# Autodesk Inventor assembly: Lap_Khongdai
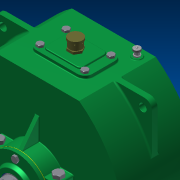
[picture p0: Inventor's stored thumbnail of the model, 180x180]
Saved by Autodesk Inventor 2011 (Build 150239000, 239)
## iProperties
Created: 2011-05
Part Number: Lap_Khongdai
Document SubType Name: Assembly
Designer: 904Chiaki
Author: 904Chiaki
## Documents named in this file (39)
- E:\2.FINISH\DOAN_CTM_final\Lap_Khongdai.iam
- E:\2.FINISH\DOAN_CTM_final\Thanhop.ipt
- E:\2.FINISH\DOAN_CTM_final\Bearing2_1.ipt
- E:\2.FINISH\DOAN_CTM_final\Bearing2_2.ipt
- E:\2.FINISH\DOAN_CTM_final\Bearing3.ipt
- E:\2.FINISH\DOAN_CTM_final\Naphop.ipt
- E:\2.FINISH\DOAN_CTM_final\Napquansat.ipt
- E:\2.FINISH\DOAN_CTM_final\Nutthonghoi.iam
- E:\2.FINISH\DOAN_CTM_final\Chotdinhvi.ipt
- E:\2.FINISH\DOAN_CTM_final\Bulongbich.ipt
- E:\2.FINISH\DOAN_CTM_final\Daiocbich.ipt
- E:\2.FINISH\DOAN_CTM_final\Vongdembich.ipt
- E:\2.FINISH\DOAN_CTM_final\BulongCanhO.ipt
- E:\2.FINISH\DOAN_CTM_final\Daioccanho.ipt
- E:\2.FINISH\DOAN_CTM_final\VongdemcanhO.ipt
- E:\2.FINISH\DOAN_CTM_final\Vitghepnapcuatham.ipt
- E:\2.FINISH\DOAN_CTM_final\VongChandau2.ipt
- E:\2.FINISH\DOAN_CTM_final\Shaft3.ipt
- E:\2.FINISH\DOAN_CTM_final\Onglot.ipt
- E:\2.FINISH\DOAN_CTM_final\VongChandau1.ipt
- E:\2.FINISH\DOAN_CTM_final\Lap1_codai\Design Accelerator\Key Connection2.iam
- E:\2.FINISH\DOAN_CTM_final\Lap1_codai\Design Accelerator\Key Connection3.iam
- E:\2.FINISH\DOAN_CTM_final\Trucvit.iam
- E:\2.FINISH\DOAN_CTM_final\Coclot1.ipt
- E:\2.FINISH\DOAN_CTM_final\Coclot2.ipt
- E:\2.FINISH\DOAN_CTM_final\NapO2.ipt
- E:\2.FINISH\DOAN_CTM_final\NapO2_2.ipt
- E:\2.FINISH\DOAN_CTM_final\Vongphot2.ipt
- E:\2.FINISH\DOAN_CTM_final\VongdemnapO2.ipt
- E:\2.FINISH\DOAN_CTM_final\NapO1.ipt
- E:\2.FINISH\DOAN_CTM_final\NapO1_2.ipt
- E:\2.FINISH\DOAN_CTM_final\VongdemNapO1.ipt
- E:\2.FINISH\DOAN_CTM_final\Vongphot1.ipt
- C:\Users\HTYCOON\Documents\Inventor\Content Center Files\R2011\en-US\DIN 910(1)\DIN 910 - M16 x 1.5.ipt
- E:\2.FINISH\DOAN_CTM_final\VitghepnapO.ipt
- E:\2.FINISH\DOAN_CTM_final\Quethamdau.ipt
- C:\Users\HTYCOON\Documents\Inventor\Content Center Files\R2011\en-US\ISO 4035(2)\ISO 4035 - M39ISO.ipt
- E:\2.FINISH\DOAN_CTM_final\Washer 18 GOST 11872-89.ipt
- E:\2.FINISH\DOAN_CTM_final\Banhvit.iam
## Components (95 placed, 37 different names)
1. Thanhop:1 — Mate:42, Flush:7, Mate:65, Mate:69, Mate:75, Mate:79, Mate:83, Mate:87, Mate:105, Mate:107, Mate:109, Mate:111, Mate:124, Angle:6, Mate:154, Mate:155, Angle:13, Angle:19, Angle:21, Angle:22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
2. DIN 628 - T1 7208B - 40 x 80 x 18:1 — Mate:179, Mate:180, Mate:182
3. ISO 355 3DB - 40 x 80 x 19.75:1 — Mate:250, Mate:251, Mate:254
4. ISO 355 3DB - 40 x 80 x 19.75:2 — Mate:248, Mate:249, Mate:251, Mate:252
5. ISO 355 2CE - 70 x 110 x 31:1 — Mate:126, Flush:12
6. ISO 355 2CE - 70 x 110 x 31:2 — Mate:123, Flush:13, Mate:128, Mate:130, Mate:260
7. Naphop:1 — Mate:42, Flush:7, Mate:45, Flush:8, Flush:9, Mate:50, Flush:10, Mate:51, Flush:11, Mate:52, Mate:53, Mate:54, Mate:55, Mate:56, Mate:57, Mate:58, Mate:59, Mate:60, Mate:61, Mate:62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
8. Napquansat:1 — Mate:43, Mate:44, Mate:45, Flush:8, Flush:9, Mate:112, Mate:113, Mate:114, Mate:115, Mate:116, Mate:117, Mate:118, Mate:119
9. Nutthonghoi:2 [sub-assembly] — Mate:43, Mate:44, Angle:32
10. ISO 2338 4 h8 x 55 - B:1 — Mate:51, Flush:11
11. ISO 2338 4 h8 x 55 - B:2 — Mate:50, Flush:10
12. ISO 4014 M14 x 70:1 — Mate:62, Mate:63, Mate:86
13. ISO 7417 M14:1 — Mate:66, Mate:67
14. ISO 7092 ST 14 - 140 HV:1 — Mate:64, Mate:65, Mate:67
15. ISO 4014 M14 x 70:2 — Mate:60, Mate:61, Mate:78
16. ISO 7417 M14:2 — Mate:70, Mate:71
17. ISO 7092 ST 14 - 140 HV:2 — Mate:68, Mate:69, Mate:71
18. ISO 4014 M14 x 70:3 — Mate:58, Mate:59, Mate:74
19. ISO 7417 M14:3 — Mate:72, Mate:73, Mate:74
20. ISO 7092 ST 14 - 140 HV:3 — Mate:72, Mate:73, Mate:75
21. ISO 4014 M14 x 70:4 — Mate:56, Mate:57, Mate:64, Mate:66
22. ISO 7417 M14:4 — Mate:76, Mate:77, Mate:78
23. ISO 7092 ST 14 - 140 HV:4 — Mate:76, Mate:77, Mate:79
24. ISO 4014 M14 x 70:5 — Mate:54, Mate:55, Mate:82
25. ISO 7417 M14:5 — Mate:80, Mate:81, Mate:82
26. ISO 7092 ST 14 - 140 HV:5 — Mate:80, Mate:81, Mate:83
27. ISO 4014 M14 x 70:6 — Mate:52, Mate:53, Mate:68, Mate:70
28. ISO 7417 M14:6 — Mate:84, Mate:85, Mate:86
29. ISO 7092 ST 14 - 140 HV:6 — Mate:84, Mate:85, Mate:87
30. ISO 4014 M16 x 120:1 — Mate:93, Mate:94, Mate:106
31. ISO 7414 M16:1 — Mate:96, Mate:97, Mate:104
32. ISO 7092 ST 16 - 140 HV:1 — Mate:96, Mate:97, Mate:105
33. ISO 4014 M16 x 120:2 — Mate:92, Mate:95, Mate:104
34. ISO 7414 M16:2 — Mate:98, Mate:99, Mate:106
35. ISO 7092 ST 16 - 140 HV:2 — Mate:98, Mate:99, Mate:107
36. ISO 4014 M16 x 120:3 — Mate:90, Mate:91, Mate:110
37. ISO 7414 M16:3 — Mate:100, Mate:101, Mate:108
38. ISO 7092 ST 16 - 140 HV:3 — Mate:100, Mate:101, Mate:109
39. ISO 4014 M16 x 120:4 — Mate:88, Mate:89, Mate:108
40. ISO 7414 M16:4 — Mate:102, Mate:103, Mate:110
41. ISO 7092 ST 16 - 140 HV:4 — Mate:102, Mate:103, Mate:111
42. ISO 4017 M10 x 20:1 — Mate:112, Mate:113, Angle:31
43. ISO 4017 M10 x 20:2 — Mate:114, Mate:117, Angle:28
44. ISO 4017 M10 x 20:3 — Mate:115, Mate:118, Angle:29
45. ISO 4017 M10 x 20:4 — Mate:116, Mate:119, Angle:30
46. VongChandau2:1 — Mate:127, Mate:129
47. VongChandau2:2 — Mate:123, Mate:130, Mate:131, Mate:133
48. Shaft:3 — Mate:124, Mate:126, Mate:127, Flush:12, Flush:13, Mate:128, Angle:6, Mate:129, Mate:131, Mate:132, Flush:14, Angle:11, Mate:140, Mate:157, Mate:158, Mate:161, Angle:25, Mate:257, Mate:259
49. Onglot:1 — Mate:132, Mate:133
50. VongChandau1:1 — Mate:181, Mate:182
51. VongChandau1:2 — Mate:183, Mate:252
52. Key Connection:1 [sub-assembly]
53. Key Connection:2 [sub-assembly] — Flush:14, Angle:11, Mate:140, Mate:258
54. Trucvit:1 [sub-assembly] — Mate:177, Mate:179, Mate:180, Mate:181, Mate:183, Mate:184, Mate:187, Mate:188, Angle:25, Mate:248, Mate:249, Mate:250, Mate:253, Angle:26, Mate:255
55. Coclot1:1 — Mate:184, Mate:185, Mate:186, Angle:23, Angle:24
56. Coclot2:1 — Mate:154, Mate:155, Angle:13, Mate:166, Mate:167, Mate:173
57. NapO2:1 — Mate:159, Angle:18, Mate:164, Mate:214, Mate:215, Mate:216, Mate:217, Mate:218, Mate:219, Mate:232, Mate:233, Mate:234, Mate:235, Mate:236, Mate:237
58. NapO2_2:1 — Mate:156, Tangent:1, Angle:15, Mate:165, Mate:202, Mate:203, Mate:204, Mate:205, Mate:206, Mate:207, Mate:244, Mate:245, Mate:260
59. Vongphot2:1 — Mate:156, Tangent:1, Mate:157
60. VongdemnapO2:1 — Mate:160, Mate:161, Angle:16, Mate:165
61. VongdemnapO2:2 — Mate:162, Mate:163, Angle:17, Mate:164
62. NapO1:1 — Mate:170, Tangent:2, Angle:21, Mate:188, Mate:189, Mate:208, Mate:209, Mate:210, Mate:211, Mate:212, Mate:213, Mate:238, Mate:239, Mate:240, Mate:241, Mate:242, Mate:243
63. NapO1_2:1 — Mate:173, Mate:174, Angle:22, Mate:220, Mate:221, Mate:222, Mate:223, Mate:224, Mate:225, Mate:226, Mate:227, Mate:228, Mate:229, Mate:230, Mate:231
64. VongdemNapO1:1 — Mate:186, Mate:187, Angle:24, Mate:189
65. Vongphot1:1 — Mate:170, Tangent:2
66. VongdemNapO1:2 — Mate:166, Mate:167, Angle:19, Mate:174
67. DIN 910 (Fine Thread) M16 x 1.5:1 — Mate:198, Mate:199
68. ISO 4017 M10 x 25:1 — Mate:220, Mate:230
69. ISO 4017 M10 x 25:2 — Mate:225, Mate:228
70. ISO 4017 M10 x 25:3 — Mate:224, Mate:227
71. ISO 4017 M10 x 25:4 — Mate:223, Mate:226
72. ISO 4017 M10 x 25:5 — Mate:222, Mate:229
73. ISO 4017 M10 x 25:6 — Mate:221, Mate:231
74. ISO 4017 M10 x 25:7 — Mate:214, Mate:236
75. ISO 4017 M10 x 25:8 — Mate:215, Mate:235
76. ISO 4017 M10 x 25:9 — Mate:216, Mate:234
77. ISO 4017 M10 x 25:10 — Mate:217, Mate:232
78. ISO 4017 M10 x 25:11 — Mate:218, Mate:233
79. ISO 4017 M10 x 25:12 — Mate:219, Mate:237
80. ISO 4017 M10 x 25:13 — Mate:208, Mate:242
81. ISO 4017 M10 x 25:14 — Mate:209, Mate:243
82. ISO 4017 M10 x 25:15 — Mate:210, Mate:238
83. ISO 4017 M10 x 25:16 — Mate:211, Mate:241
84. ISO 4017 M10 x 25:17 — Mate:212, Mate:240
85. ISO 4017 M10 x 25:18 — Mate:213, Mate:239
86. ISO 4017 M10 x 25:19 — Mate:202, Flush:19, Mate:245
87. ISO 4017 M10 x 25:20 — Mate:207, Flush:16, Flush:18
88. ISO 4017 M10 x 25:21 — Mate:206, Flush:16, Flush:17
89. ISO 4017 M10 x 25:22 — Mate:205, Flush:17
90. ISO 4017 M10 x 25:23 — Mate:204, Mate:244
91. ISO 4017 M10 x 25:24 — Mate:203, Flush:18, Flush:19
92. Quethamdau:1 — Mate:246, Mate:247, Angle:27
93. ISO 4035 M39:1 — Mate:255, Mate:256
94. Washer GOST 11872-89 18:1 — Mate:253, Mate:254, Angle:26, Mate:256
95. Banhvit:1 [sub-assembly] — Mate:257, Mate:258, Mate:259
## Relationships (209: Mate 175, Angle 20, Flush 12, Tangent 2)
- Mate:42: Thanhop:1 ↔ Naphop:1
- Flush:7: Thanhop:1 ↔ Naphop:1
- Mate:43: Napquansat:1 ↔ Nutthonghoi:2
- Mate:44: Napquansat:1 ↔ Nutthonghoi:2
- Mate:45: Naphop:1 ↔ Napquansat:1
- Flush:8: Naphop:1 ↔ Napquansat:1
- Flush:9: Naphop:1 ↔ Napquansat:1
- Mate:50: Naphop:1 ↔ ISO 2338 4 h8 x 55 - B:2
- Flush:10: Naphop:1 ↔ ISO 2338 4 h8 x 55 - B:2
- Mate:51: Naphop:1 ↔ ISO 2338 4 h8 x 55 - B:1
- Flush:11: Naphop:1 ↔ ISO 2338 4 h8 x 55 - B:1
- Mate:52: Naphop:1 ↔ ISO 4014 M14 x 70:6
- Mate:53: Naphop:1 ↔ ISO 4014 M14 x 70:6
- Mate:54: Naphop:1 ↔ ISO 4014 M14 x 70:5
- Mate:55: Naphop:1 ↔ ISO 4014 M14 x 70:5
- Mate:56: Naphop:1 ↔ ISO 4014 M14 x 70:4
- Mate:57: Naphop:1 ↔ ISO 4014 M14 x 70:4
- Mate:58: Naphop:1 ↔ ISO 4014 M14 x 70:3
- Mate:59: Naphop:1 ↔ ISO 4014 M14 x 70:3
- Mate:60: Naphop:1 ↔ ISO 4014 M14 x 70:2
- Mate:61: Naphop:1 ↔ ISO 4014 M14 x 70:2
- Mate:62: Naphop:1 ↔ ISO 4014 M14 x 70:1
- Mate:63: Naphop:1 ↔ ISO 4014 M14 x 70:1
- Mate:64: ISO 7092 ST 14 - 140 HV:1 ↔ ISO 4014 M14 x 70:4
- Mate:65: Thanhop:1 ↔ ISO 7092 ST 14 - 140 HV:1
- Mate:66: ISO 7417 M14:1 ↔ ISO 4014 M14 x 70:4
- Mate:67: ISO 7417 M14:1 ↔ ISO 7092 ST 14 - 140 HV:1
- Mate:68: ISO 7092 ST 14 - 140 HV:2 ↔ ISO 4014 M14 x 70:6
- Mate:69: Thanhop:1 ↔ ISO 7092 ST 14 - 140 HV:2
- Mate:70: ISO 7417 M14:2 ↔ ISO 4014 M14 x 70:6
- Mate:71: ISO 7417 M14:2 ↔ ISO 7092 ST 14 - 140 HV:2
- Mate:72: ISO 7417 M14:3 ↔ ISO 7092 ST 14 - 140 HV:3
- Mate:73: ISO 7417 M14:3 ↔ ISO 7092 ST 14 - 140 HV:3
- Mate:74: ISO 4014 M14 x 70:3 ↔ ISO 7417 M14:3
- Mate:75: Thanhop:1 ↔ ISO 7092 ST 14 - 140 HV:3
- Mate:76: ISO 7417 M14:4 ↔ ISO 7092 ST 14 - 140 HV:4
- Mate:77: ISO 7417 M14:4 ↔ ISO 7092 ST 14 - 140 HV:4
- Mate:78: ISO 4014 M14 x 70:2 ↔ ISO 7417 M14:4
- Mate:79: Thanhop:1 ↔ ISO 7092 ST 14 - 140 HV:4
- Mate:80: ISO 7417 M14:5 ↔ ISO 7092 ST 14 - 140 HV:5
- Mate:81: ISO 7417 M14:5 ↔ ISO 7092 ST 14 - 140 HV:5
- Mate:82: ISO 4014 M14 x 70:5 ↔ ISO 7417 M14:5
- Mate:83: Thanhop:1 ↔ ISO 7092 ST 14 - 140 HV:5
- Mate:84: ISO 7417 M14:6 ↔ ISO 7092 ST 14 - 140 HV:6
- Mate:85: ISO 7417 M14:6 ↔ ISO 7092 ST 14 - 140 HV:6
- Mate:86: ISO 4014 M14 x 70:1 ↔ ISO 7417 M14:6
- Mate:87: Thanhop:1 ↔ ISO 7092 ST 14 - 140 HV:6
- Mate:88: Naphop:1 ↔ ISO 4014 M16 x 120:4
- Mate:89: Naphop:1 ↔ ISO 4014 M16 x 120:4
- Mate:90: Naphop:1 ↔ ISO 4014 M16 x 120:3
- Mate:91: Naphop:1 ↔ ISO 4014 M16 x 120:3
- Mate:92: Naphop:1 ↔ ISO 4014 M16 x 120:2
- Mate:93: Naphop:1 ↔ ISO 4014 M16 x 120:1
- Mate:94: Naphop:1 ↔ ISO 4014 M16 x 120:1
- Mate:95: Naphop:1 ↔ ISO 4014 M16 x 120:2
- Mate:96: ISO 7414 M16:1 ↔ ISO 7092 ST 16 - 140 HV:1
- Mate:97: ISO 7414 M16:1 ↔ ISO 7092 ST 16 - 140 HV:1
- Mate:98: ISO 7414 M16:2 ↔ ISO 7092 ST 16 - 140 HV:2
- Mate:99: ISO 7414 M16:2 ↔ ISO 7092 ST 16 - 140 HV:2
- Mate:100: ISO 7414 M16:3 ↔ ISO 7092 ST 16 - 140 HV:3
- Mate:101: ISO 7414 M16:3 ↔ ISO 7092 ST 16 - 140 HV:3
- Mate:102: ISO 7414 M16:4 ↔ ISO 7092 ST 16 - 140 HV:4
- Mate:103: ISO 7414 M16:4 ↔ ISO 7092 ST 16 - 140 HV:4
- Mate:104: ISO 7414 M16:1 ↔ ISO 4014 M16 x 120:2
- Mate:105: Thanhop:1 ↔ ISO 7092 ST 16 - 140 HV:1
- Mate:106: ISO 4014 M16 x 120:1 ↔ ISO 7414 M16:2
- Mate:107: Thanhop:1 ↔ ISO 7092 ST 16 - 140 HV:2
- Mate:108: ISO 7414 M16:3 ↔ ISO 4014 M16 x 120:4
- Mate:109: Thanhop:1 ↔ ISO 7092 ST 16 - 140 HV:3
- Mate:110: ISO 4014 M16 x 120:3 ↔ ISO 7414 M16:4
- Mate:111: Thanhop:1 ↔ ISO 7092 ST 16 - 140 HV:4
- Mate:112: Napquansat:1 ↔ ISO 4017 M10 x 20:1
- Mate:113: Napquansat:1 ↔ ISO 4017 M10 x 20:1
- Mate:114: Napquansat:1 ↔ ISO 4017 M10 x 20:2
- Mate:115: Napquansat:1 ↔ ISO 4017 M10 x 20:3
- Mate:116: Napquansat:1 ↔ ISO 4017 M10 x 20:4
- Mate:117: Napquansat:1 ↔ ISO 4017 M10 x 20:2
- Mate:118: Napquansat:1 ↔ ISO 4017 M10 x 20:3
- Mate:119: Napquansat:1 ↔ ISO 4017 M10 x 20:4
- Mate:123: ISO 355 2CE - 70 x 110 x 31:2 ↔ VongChandau2:2
- Mate:124: Thanhop:1 ↔ Shaft:3
- Mate:126: ISO 355 2CE - 70 x 110 x 31:1 ↔ Shaft:3
- Mate:127: VongChandau2:1 ↔ Shaft:3
- Flush:12: ISO 355 2CE - 70 x 110 x 31:1 ↔ Shaft:3
- Flush:13: ISO 355 2CE - 70 x 110 x 31:2 ↔ Shaft:3
- Mate:128: ISO 355 2CE - 70 x 110 x 31:2 ↔ Shaft:3
- Angle:6: Thanhop:1 ↔ Shaft:3
- Mate:129: VongChandau2:1 ↔ Shaft:3
- Mate:130: ISO 355 2CE - 70 x 110 x 31:2 ↔ VongChandau2:2
- Mate:131: VongChandau2:2 ↔ Shaft:3
- Mate:132: Shaft:3 ↔ Onglot:1
- Mate:133: VongChandau2:2 ↔ Onglot:1
- Flush:14: Shaft:3 ↔ Key Connection:2
- Angle:11: Shaft:3 ↔ Key Connection:2
- Mate:140: Shaft:3 ↔ Key Connection:2
- Mate:154: Thanhop:1 ↔ Coclot2:1
- Mate:155: Thanhop:1 ↔ Coclot2:1
- Angle:13: Thanhop:1 ↔ Coclot2:1
- Mate:156: NapO2_2:1 ↔ Vongphot2:1
- Tangent:1: NapO2_2:1 ↔ Vongphot2:1
- Mate:157: Shaft:3 ↔ Vongphot2:1
- Mate:158: Naphop:1 ↔ Shaft:3
- Angle:15: Naphop:1 ↔ NapO2_2:1
- Mate:159: Naphop:1 ↔ NapO2:1
- Mate:160: Naphop:1 ↔ VongdemnapO2:1
- Mate:161: Shaft:3 ↔ VongdemnapO2:1
- Angle:16: Naphop:1 ↔ VongdemnapO2:1
- Mate:162: Naphop:1 ↔ VongdemnapO2:2
- Mate:163: Naphop:1 ↔ VongdemnapO2:2
- Angle:17: Naphop:1 ↔ VongdemnapO2:2
- Angle:18: Naphop:1 ↔ NapO2:1
- Mate:164: NapO2:1 ↔ VongdemnapO2:2
- Mate:165: NapO2_2:1 ↔ VongdemnapO2:1
- Mate:166: Coclot2:1 ↔ VongdemNapO1:2
- Mate:167: Coclot2:1 ↔ VongdemNapO1:2
- Angle:19: Thanhop:1 ↔ VongdemNapO1:2
- Mate:170: NapO1:1 ↔ Vongphot1:1
- Tangent:2: NapO1:1 ↔ Vongphot1:1
- Angle:21: Thanhop:1 ↔ NapO1:1
- Mate:173: Coclot2:1 ↔ NapO1_2:1
- Mate:174: NapO1_2:1 ↔ VongdemNapO1:2
- Angle:22: Thanhop:1 ↔ NapO1_2:1
- Mate:177: Thanhop:1 ↔ Trucvit:1
- Mate:179: DIN 628 - T1 7208B - 40 x 80 x 18:1 ↔ Trucvit:1
- Mate:180: DIN 628 - T1 7208B - 40 x 80 x 18:1 ↔ Trucvit:1
- Mate:181: VongChandau1:1 ↔ Trucvit:1
- Mate:182: DIN 628 - T1 7208B - 40 x 80 x 18:1 ↔ VongChandau1:1
- Mate:183: VongChandau1:2 ↔ Trucvit:1
- Mate:184: Trucvit:1 ↔ Coclot1:1
- Mate:185: Thanhop:1 ↔ Coclot1:1
- Mate:186: Coclot1:1 ↔ VongdemNapO1:1
- Mate:187: Trucvit:1 ↔ VongdemNapO1:1
- Angle:23: Thanhop:1 ↔ Coclot1:1
- Angle:24: Coclot1:1 ↔ VongdemNapO1:1
- Mate:188: Trucvit:1 ↔ NapO1:1
- Mate:189: NapO1:1 ↔ VongdemNapO1:1
- Angle:25: Shaft:3 ↔ Trucvit:1
- Mate:198: Thanhop:1 ↔ DIN 910 (Fine Thread) M16 x 1.5:1
- Mate:199: Thanhop:1 ↔ DIN 910 (Fine Thread) M16 x 1.5:1
- Mate:202: NapO2_2:1 ↔ ISO 4017 M10 x 25:19
- Mate:203: NapO2_2:1 ↔ ISO 4017 M10 x 25:24
- Mate:204: NapO2_2:1 ↔ ISO 4017 M10 x 25:23
- Mate:205: NapO2_2:1 ↔ ISO 4017 M10 x 25:22
- Mate:206: NapO2_2:1 ↔ ISO 4017 M10 x 25:21
- Mate:207: NapO2_2:1 ↔ ISO 4017 M10 x 25:20
- Mate:208: NapO1:1 ↔ ISO 4017 M10 x 25:13
- Mate:209: NapO1:1 ↔ ISO 4017 M10 x 25:14
- Mate:210: NapO1:1 ↔ ISO 4017 M10 x 25:15
- Mate:211: NapO1:1 ↔ ISO 4017 M10 x 25:16
- Mate:212: NapO1:1 ↔ ISO 4017 M10 x 25:17
- Mate:213: NapO1:1 ↔ ISO 4017 M10 x 25:18
- Mate:214: NapO2:1 ↔ ISO 4017 M10 x 25:7
- Mate:215: NapO2:1 ↔ ISO 4017 M10 x 25:8
- Mate:216: NapO2:1 ↔ ISO 4017 M10 x 25:9
- Mate:217: NapO2:1 ↔ ISO 4017 M10 x 25:10
- Mate:218: NapO2:1 ↔ ISO 4017 M10 x 25:11
- Mate:219: NapO2:1 ↔ ISO 4017 M10 x 25:12
- Mate:220: NapO1_2:1 ↔ ISO 4017 M10 x 25:1
- Mate:221: NapO1_2:1 ↔ ISO 4017 M10 x 25:6
- Mate:222: NapO1_2:1 ↔ ISO 4017 M10 x 25:5
- Mate:223: NapO1_2:1 ↔ ISO 4017 M10 x 25:4
- Mate:224: NapO1_2:1 ↔ ISO 4017 M10 x 25:3
- Mate:225: NapO1_2:1 ↔ ISO 4017 M10 x 25:2
- Mate:226: NapO1_2:1 ↔ ISO 4017 M10 x 25:4
- Mate:227: NapO1_2:1 ↔ ISO 4017 M10 x 25:3
- Mate:228: NapO1_2:1 ↔ ISO 4017 M10 x 25:2
- Mate:229: NapO1_2:1 ↔ ISO 4017 M10 x 25:5
- Mate:230: NapO1_2:1 ↔ ISO 4017 M10 x 25:1
- Mate:231: NapO1_2:1 ↔ ISO 4017 M10 x 25:6
- Mate:232: NapO2:1 ↔ ISO 4017 M10 x 25:10
- Mate:233: NapO2:1 ↔ ISO 4017 M10 x 25:11
- Mate:234: NapO2:1 ↔ ISO 4017 M10 x 25:9
- Mate:235: NapO2:1 ↔ ISO 4017 M10 x 25:8
- Mate:236: NapO2:1 ↔ ISO 4017 M10 x 25:7
- Mate:237: NapO2:1 ↔ ISO 4017 M10 x 25:12
- Mate:238: NapO1:1 ↔ ISO 4017 M10 x 25:15
- Mate:239: NapO1:1 ↔ ISO 4017 M10 x 25:18
- Mate:240: NapO1:1 ↔ ISO 4017 M10 x 25:17
- Mate:241: NapO1:1 ↔ ISO 4017 M10 x 25:16
- Mate:242: NapO1:1 ↔ ISO 4017 M10 x 25:13
- Mate:243: NapO1:1 ↔ ISO 4017 M10 x 25:14
- Mate:244: NapO2_2:1 ↔ ISO 4017 M10 x 25:23
- Flush:16: ISO 4017 M10 x 25:20 ↔ ISO 4017 M10 x 25:21
- Flush:17: ISO 4017 M10 x 25:21 ↔ ISO 4017 M10 x 25:22
- Flush:18: ISO 4017 M10 x 25:20 ↔ ISO 4017 M10 x 25:24
- Flush:19: ISO 4017 M10 x 25:19 ↔ ISO 4017 M10 x 25:24
- Mate:245: NapO2_2:1 ↔ ISO 4017 M10 x 25:19
- Mate:246: Naphop:1 ↔ Quethamdau:1
- Mate:247: Naphop:1 ↔ Quethamdau:1
- Mate:248: ISO 355 3DB - 40 x 80 x 19.75:2 ↔ Trucvit:1
- Mate:249: ISO 355 3DB - 40 x 80 x 19.75:2 ↔ Trucvit:1
- Mate:250: ISO 355 3DB - 40 x 80 x 19.75:1 ↔ Trucvit:1
- Mate:251: ISO 355 3DB - 40 x 80 x 19.75:1 ↔ ISO 355 3DB - 40 x 80 x 19.75:2
- Mate:252: ISO 355 3DB - 40 x 80 x 19.75:2 ↔ VongChandau1:2
- Mate:253: Trucvit:1 ↔ Washer GOST 11872-89 18:1
- Mate:254: ISO 355 3DB - 40 x 80 x 19.75:1 ↔ Washer GOST 11872-89 18:1
- Angle:26: Trucvit:1 ↔ Washer GOST 11872-89 18:1
- Mate:255: Trucvit:1 ↔ ISO 4035 M39:1
- Mate:256: ISO 4035 M39:1 ↔ Washer GOST 11872-89 18:1
- Mate:257: Shaft:3 ↔ Banhvit:1
- Mate:258: Key Connection:2 ↔ Banhvit:1
- Mate:259: Shaft:3 ↔ Banhvit:1
- Mate:260: ISO 355 2CE - 70 x 110 x 31:2 ↔ NapO2_2:1
- Angle:27: Naphop:1 ↔ Quethamdau:1
- Angle:28: Naphop:1 ↔ ISO 4017 M10 x 20:2
- Angle:29: Naphop:1 ↔ ISO 4017 M10 x 20:3
- Angle:30: Naphop:1 ↔ ISO 4017 M10 x 20:4
- Angle:31: Naphop:1 ↔ ISO 4017 M10 x 20:1
- Angle:32: Naphop:1 ↔ Nutthonghoi:2
